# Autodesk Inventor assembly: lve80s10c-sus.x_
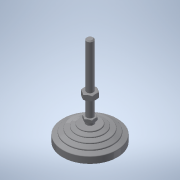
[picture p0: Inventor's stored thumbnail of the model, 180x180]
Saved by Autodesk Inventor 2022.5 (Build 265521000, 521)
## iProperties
Part Number: lve80s10c-sus.x_
Material: 一般
Document SubType Name: Assembly
Designer: ImaoCorp
Sending System: SOLIDWORKS 2017-2017317
MC: AMD64
MC_MODEL: Intel64 Family 6 Model 60 Stepping 3, GenuineIntel
OS: Windows_NT
FRU: Parasolid Version 29.0, build 201,  4-17-2017
FORMAT: text
GUISE: transmit
KEY: lve80s10c-sus
FILE: lve80s10c-sus.x_t
DATE: Mon Jul 01 18:21:52 2019
Author: ImaoCorp
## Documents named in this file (3)
- X:\14_SW2022-Inv2022\00_全2023-1023新製品(TCC)まで\l\lve80s10c-sus\LVE80S10C-SUS.iam
- X:\14_SW2022-Inv2022\00_全2023-1023新製品(TCC)まで\l\lve80s10c-sus\lve80s10c-sus_01.ipt
- X:\14_SW2022-Inv2022\00_全2023-1023新製品(TCC)まで\l\lve80s10c-sus\lve80s10c-sus_02.ipt
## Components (2 placed, 2 different names)
1. lve80s10c-sus_01
2. lve80s10c-sus_02
